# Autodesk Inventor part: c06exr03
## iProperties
Shininess: 77.0
Length Units: 11269
Angle Units: 11279
Time Units: 11290
Mass Units: 11283
Length Display Precision: 3
Angle Display Precision: 2
Created: 2001-12
Part Number: c06exr03
Document SubType Name: Modeling
Density: 1 g/cm^3
Density: 0.0
Volumn: 0.0
Area: 0.0
PropertySet Name: Model Information
Control State: 0
Master: False
Checked Out: False
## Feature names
1. Extrusion1
2. Extrusion2
3. Extrusion3
4. Extrusion4
5. Mirror1
6. Hole1
